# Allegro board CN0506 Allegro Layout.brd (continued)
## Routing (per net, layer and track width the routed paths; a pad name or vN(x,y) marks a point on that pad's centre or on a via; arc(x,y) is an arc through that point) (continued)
VDD_0P9: length 39.6
  TOP w0.508: C57.1 49.26,15.29 C58.1 50.01,15.27 ; C57.1 49.81,16.28 ; C57.1 49.26,16.87 ; 47.86,42.99 47.86,43 C22.1 46.83,43.78 ; 47.86,42.99 47.86,44.15 47.72,44.29 ; 47.86,42.99 C23.1 ; 49.24,39.83 v1(50.1,39.83) ; 49.24,39.83 C11.1 ; 49.24,39.83 C10.1 ; 46.2,36.36 C1.1 46.22,37.06 C2.1 ; C62.2 51.05,21.2 ; C62.2 49.79,22.25 ; C62.2 52.31,22.25 ; 49.77,47.32 C15.2 ; C15.2 52.46,47.32 ; C15.2 51.02,46.15 ; C61.1 48.51,22.3 ; C61.1 49.49,23.13 ; C61.1 47.53,23.13 ; 47.87,18.99 C69.1 46.86,18.43 ; 47.24,11.84 C49.1 47.22,12.48 C48.1 46.22,11.75 ; C14.1 49.59,47.82 ; C14.1 48.61,46.79 ; C14.1 47.63,47.82 ; C10.1 49.24,41.43 ; C10.1 49.78,40.84 ; 46.86,18.43 C70.1 ; 46.86,18.43 46.86,18.95 ; v1(47.21,35.98) C2.1 ; C2.1 47.87,37.06
  BOTTOM w0.279: U1.4 47.1,11.7 v1(46.99,11.58) ; U1.36 v1(50.28,15.27) ; v1(47.21,35.98) 47.21,36.12 47.07,36.26 U2.4 ; U1.28 v1(47.6,19.46)
  BOTTOM w0.305: U2.28 47.57,44.2 47.68,44.31 v1(47.68,44.32) ; v1(50.1,39.83) 50.09,39.83 U2.36
  BOTTOM w0.508: R55.2 10.1,51.5 ; R55.2 9.3,50.8 ; R55.2 v1(8.19,51.5)
  vias: v1(8.19,50.71) v1(18.35,57.19) v1(19.17,57.19) v1(20,57.15) v1(20,56.2) v1(20,55.18) v1(20.51,62.99) v1(20.51,62.1) v1(20.51,61.09) v1(20.51,60.07) v1(20.51,59.31) v1(20.89,57.15) v1(20.89,56.2) v1(20.89,55.18) v1(21.4,62.99) v1(21.4,62.1) v1(21.4,61.09) v1(21.4,60.07) v1(21.4,59.31)
VDD_ADJ: length 77.3
  TOP w0.203: U14.8 57.43,46.74 57.59,46.9 v1(57.59,47.79)
  TOP w0.229: U9.8 57.11,30.36 57.34,30.59 v1(57.34,30.92)
  TOP w0.305: U10.1 30.15,7.62 v1(30.43,7.34) ; U11.1 30.11,26.03 30.41,25.73 v1(30.41,25.53) ; U12.1 30.33,31.75 v1(30.54,31.54) ; U13.1 30.15,50.16 v1(30.43,49.89)
  TOP w0.508: R84.1 v1(58.54,28.62) ; 45.84,18.43 45.84,19.33 v1(46.05,19.54) ; 45.84,18.43 C68.1 ; 45.84,18.43 C66.1 ; C75.1 C76.1 62.16,9.78 61.62,10.33 v1(61.47,10.33) ; R8.1 v1(63.55,54.13) ; R80.1 v1(63.43,35.15) ; R77.1 v1(57.46,24.17) ; 44.52,23.65 C18.1 ; C18.1 42.46,23.65 ; C18.1 43.49,22.77 ; 49.26,13.26 C51.1 ; 49.26,13.26 C52.1 ; 49.26,13.26 49.26,13.23 49.69,13.23 v1(50.1,12.83) ; v1(60.2,9.06) 60.2,9.06 59.68,9.57 C74.1 ; R74.1 v1(68.01,33.06) ; C20.1 49.22,38.79 C13.1 49.22,37.64 v1(49.72,37.14) ; 45.7,21.99 45.7,21.03 ; 45.7,21.99 45.56,21.84 v1(44.51,21.84) ; 45.7,21.99 C19.2 45.51,22.71 44.51,22.71 ; 43.92,47.95 C65.1 ; C65.1 41.86,47.95 ; C65.1 42.9,47.04 ; 44.38,47.19 C67.2 45.69,46.09 ; v1(45.94,44.15) 45.82,44.02 C21.1 45.8,43 C12.1 ; R16.1 v1(63.31,50.84) ; R18.1 v1(56.07,50.84) ; R11.1 v1(56.19,43.22) ; C59.1 49.89,17.81 C60.1 49.93,17.81 50.6,17.81 v1(50.73,17.95) ; R86.1 v1(56.96,34.59) ; C5.1 48.89,42.52 C4.1 50.39,42.52 50.58,42.71 v1(50.59,42.71) ; R82.1 58.87,35.08 v1(58.61,35.35) ; R20.1 v1(56.07,53.38) ; R14.1 v1(63.56,46.53)
  BOTTOM w0.279: v1(46.05,19.54) 46.1,19.49 U1.25 ; v1(49.72,37.14) 49.72,37.57 49.45,37.83 U2.40 ; U1.31 50.05,17.77 50.22,17.95 v1(50.73,17.95) ; v1(50.1,12.83) 49.65,13.27 U1.40
  BOTTOM w0.305: U3.1 54.46,32.49 54.46,32.5 54.62,32.5 54.93,32.8 v1(54.93,32.98) ; v1(45.94,44.15) 46.07,44.02 U2.25 ; v1(50.59,42.71) 50.58,42.71 50.2,42.33 U2.31
  BOTTOM w0.508: 47.13,63.8 47.07,63.8 ; 47.13,63.8 v1(47.93,63.8) 47.91,63.82 C43.1 47.07,63.8 ; 47.13,63.8 47.13,63.79 v1(45.22,63.79) L2.2 ; 47.07,63.8 46.05,63.8 C41.1 v1(46.03,62.9) ; v1(35.32,63.82) C47.1 C45.1 ; R31.1 49.88,49.94 v1(49.88,51.56) ; R33.1 v1(49.97,26.3) ; v1(44.21,47.63) 44.45,47.87 R5.1 ; R6.1 v1(43.62,50.88) ; v1(43.96,22.61) 44.21,22.85 R71.1 ; v1(43.69,26.62) 43.62,26.62 R72.1 ; R37.1 46.83,49.94 v1(46.83,51.56) ; v1(32.23,64.81) L3.2 33.56,63.79 C45.1 ; P8.G39 v1(61.47,10.33) ; v1(33.59,62.9) C45.1 ; R39.1 v1(46.92,26.3) ; P8.H40 v1(60.2,9.06)
  vias: v1(42.51,46.81) v1(42.56,22.61) v1(44.23,46.86)
AUX_3P3: length 33.1
  TOP w0.305: U14.1 55.56,46.78 v1(55.24,47.09) ; U7.3 v1(67.88,17.53) ; U7.8 v1(66.58,26.84) ; U8.8 70.65,23.72 v1(70.42,23.49)
  TOP w0.508: Y1.6 41.11,30.91 C24.1 v1(42.86,30.16) ; Y2.6 C25.1 40.42,22.13 v1(40.17,21.88) ; v1(64.04,19.25) 64.45,18.84 C78.1
  BOTTOM w0.203: P8.D32 v1(64.04,19.25) ; v1(52.9,33.06) 52.9,32.66 53.1,32.46 U3.8 ; 30.32,28.31 30.39,28.23 R47.2
  BOTTOM w0.254: C27.1 22.16,30 U15.4
  BOTTOM w0.508: 52.35,50.64 Y3.1 Y3.6 ; Y3.6 53.95,50.64 ; Y3.6 54.7,51.44 ; C73.1 52.51,49.94 ; C73.1 53.78,49.94 ; C73.1 53.15,50.54 ; R26.1 v1(21.91,31.09) 21.9,31.09 C27.1 ; R49.2 30.39,29.38 ; R49.2 R47.2 ; R49.2 R76.1 30.39,30.52 ; R48.1 v1(20.9,28.3) ; 30.59,28.31 29.85,28.31 R47.2 ; U5.5 49.54,34.71 v1(50.07,35.25) ; R13.1 R47.2 ; v1(49.46,31.79) 49.46,31.41 49.08,31.03 U6.5 48.7,31.41 v1(48.7,31.79)
  vias: v1(31.05,29.63) v1(31.17,28.23) v1(32.19,30.9) v1(32.19,29.63) v1(32.19,27.34) v1(54.03,50.33) v1(54.03,49.57)
FB: length 4.2
  BOTTOM w0.203: U4.3 10.73,54.23 9.97,53.47 9.56,53.47 R55.1 7.75,53.2 R54.2
FMC_RESET_A: length 61
  BOTTOM w0.203: R58.1 49.04,53.09 50.83,54.88 50.83,61.08 52.01,62.26 R60.2 C42.1 57.67,63.78 62.04,59.42 62.04,36.23 61.54,35.74 60.19,35.74 P8.H19 57.84,36.36 56.32,34.84 56.32,33.31 55.08,32.07 54.26,32.07 U3.2
FMC_RESET_B: length 74.4
  BOTTOM w0.203: R58.2 44.9,54.05 41.59,57.36 41.59,61.63 40.96,62.26 R64.2 C46.1 40.94,63.78 43.49,66.33 55.7,66.33 62.67,59.36 62.67,35.09 62.02,34.44 60.21,34.44 P8.H20 59.14,35.09 58.87,34.82 58.83,34.82 55.67,31.66 U3.3
FPGA_LED_0_A: length 20.1
  TOP w0.203: v1(61.47,44.62) 60.89,44.04 60.89,43.22 55.94,38.27 55.94,33.82 56.04,33.72 56.04,32.07 56.32,31.79 57.59,31.79 57.96,31.42 57.96,30.61 57.31,29.96 U9.7
  BOTTOM w0.203: P8.G12 v1(61.47,44.62)
FPGA_LED_0_B: length 9.4
  TOP w0.203: v1(64.01,30.65) 63.33,31.32 58.81,31.32 58.37,30.88 58.37,30.28 57.66,29.57 56.92,29.57 U9.6
  BOTTOM w0.203: P8.D23 v1(64.01,30.65)
GA0: length 11.2
  TOP w0.203: U8.1 70.65,20.13 69.91,20.87 67.12,20.87 66.58,20.33 U7.1 66.58,17.41 65.93,16.76 65.92,16.76 65.84,16.68 v1(65.28,16.68)
  BOTTOM w0.203: P8.C34 v1(65.28,16.68)
GA1: length 15.7
  TOP w0.203: U8.2 71.3,17.94 70.96,17.6 69.88,17.6 69.53,17.95 69.53,20.16 69.33,20.36 67.44,20.36 67.23,20.16 U7.2 67.23,17.05 66.3,16.12 64.72,16.12 v1(64.01,15.41)
  BOTTOM w0.203: P8.D35 v1(64.01,15.41)
GP_CLK/RX_ER_A: length 24
  L6_SIG w0.203: v1(48.86,45.84) 56.79,45.84 57.51,46.56 61.82,46.56 64.01,48.75 v1(64.01,49.7)
  BOTTOM w0.203: U2.27 47.07,44.64 48.28,45.84 v1(48.86,45.84) 49.55,45.84 49.85,46.15 R29.1 ; v1(64.01,49.7) P8.D9
GP_CLK/RX_ER_B: length 40.4
  L6_SIG w0.203: v1(49.08,21.88) 58.6,21.88 59.04,22.31 68.82,22.31 69.66,23.15 69.66,30.08 v1(65.24,34.49)
  BOTTOM w0.203: R30.1 49.94,21.88 v1(49.08,21.88) 47.04,19.84 47.04,19.23 47.1,19.17 U1.27 ; v1(65.24,34.49) 64.64,33.89 P8.D21
INT_N/CRS_A: length 28.6
  L6_SIG w0.203: P4.1 44.18,44.77 44.18,43.57 45.58,42.18 49.77,42.18 50.05,41.89 57,41.89 58.45,43.35 v1(61.47,43.35)
  BOTTOM w0.203: P8.G13 v1(61.47,43.35) ; R6.2 43.26,48.55 43.26,46.46 43.28,46.45 P4.1 44.23,44.72 44.23,43.67 44.57,43.33 U2.22
INT_N/CRS_B: length 36.7
  L6_SIG w0.203: P7.1 44.01,21.36 44.26,21.12 45.53,21.12 47.43,23.03 56.32,23.03 56.91,23.61 59.18,23.61 60.91,25.33 60.91,25.8 61.39,26.28 65.64,26.28 65.85,26.48 65.85,28.49 65.52,28.82 64.57,28.82 v1(64.01,29.38)
  BOTTOM w0.203: U1.22 44.6,19.27 44.27,19.61 44.27,20.17 43.18,21.26 P7.1 43.23,21.41 43.23,23.62 R72.2 ; P8.D24 v1(64.01,29.38)
LED_0_A: length 49.9
  TOP w0.203: DS4.C 21.25,48.52 26.79,48.52 27.55,47.76 33.92,47.76 34.3,48.14 36.59,48.14 38.94,45.79 v1(40.25,45.79) ; U9.2 53.09,29.96 v1(52.89,29.76)
  L3_SIG w0.229: v1(52.89,29.76) 49.34,29.76 44.13,34.96 44.13,42.58 40.92,45.79 v1(40.25,45.79)
  BOTTOM w0.203: v1(40.25,45.79) 41.29,45.79 R4.2 R42.1
LED_0_B: length 50.8
  TOP w0.203: v1(54.42,27.22) 54.42,28.91 55.06,29.56 U9.3 ; DS2.C 20.19,27.74 25.27,27.74 25.52,27.99
  TOP w0.254: v1(39.3,20.95) 35.54,20.95 33.97,22.52 33.97,26.58 31.81,28.74 31.49,28.74 31.37,28.87 26.4,28.87 25.52,27.99
  L3_SIG w0.229: v1(54.42,27.22) 45.17,27.22 41.59,23.63 41.59,22.43 40.1,20.95 v1(39.3,20.95)
  BOTTOM w0.203: v1(39.3,20.95) R70.2 R41.1
LED_AL_A: length 23.6
  TOP w0.203: U13.6 27.46,51 26.6,51.86 10.41,51.86 M2.14
LED_AL_A_C2M: length 65
  TOP w0.203: v1(31.3,51.22) 31.08,51 U13.3
  L6_SIG w0.203: v1(31.3,51.22) 31.3,51.86 30.35,52.81 30.35,56.88 31.29,57.82 56.19,57.82 57.33,56.69 65.51,56.69 67.12,55.08 67.12,39.16 66.23,38.27 v1(65.28,38.27)
  BOTTOM w0.203: P8.D18 v1(65.28,38.27)
LED_AL_C: length 21.4
  TOP w0.203: M2.13 8.19,47.1 8.19,48.95 10.59,51.35 23.51,51.35 24.51,50.34 R25.2
LED_AL_C_C2M: length 57.6
  TOP w0.203: v1(31.3,50.2) 30.91,50.6 U13.2
  L6_SIG w0.203: v1(64.01,38.27) P8.D17 65.46,38.9 65.99,39.43 65.99,40.57 65.99,40.57 65.99,41.04 65.99,41.04 65.99,43.11 65.99,43.12 65.99,43.58 65.99,43.58 65.99,44.38 65.99,44.39 65.99,44.85 65.99,44.85 65.99,45.65 65.99,45.65 65.99,46.12 65.99,46.12 65.99,48.19 65.99,48.2 65.99,48.66 65.99,48.66 65.99,49.46 65.99,49.47 65.99,49.93 65.99,49.93 65.99,50.73 65.99,50.73 65.99,51.2 65.99,51.2 65.99,53.27 65.99,53.28 65.99,53.74 65.99,53.74 65.99,54.89 65.45,55.42 59.96,55.42 59.9,55.36 36.46,55.36 v1(31.3,50.2)
  BOTTOM w0.203: P8.D17 v1(64.01,38.27)
LED_AR_A: length 25.5
  TOP w0.203: U12.6 28.65,32.58 28.64,32.6 27.79,32.6 27.38,33.01 23.54,33.01 22.92,32.38 10.64,32.38 8.31,34.71 8.31,36.41 M2.12
LED_AR_A_C2M: length 38.3
  TOP w0.203: v1(31.73,33.95) 31.73,33.3 31.01,32.58 U12.3
  L6_SIG w0.203: v1(31.73,33.95) 31.73,34.79 35.34,38.39 49.46,38.39 50.3,39.23 51.04,39.23 52.7,37.57 60.39,37.57 60.83,38.01 60.83,38.9 v1(61.47,39.54)
  BOTTOM w0.203: P8.G16 v1(61.47,39.54)
LED_AR_C: length 18.9
  TOP w0.203: M2.11 10.35,31.84 24.42,31.84 R24.2
LED_AR_C_C2M: length 40.6
  TOP w0.203: v1(32.95,33.95) 31.18,32.18 29.93,32.18 29.92,32.19 U12.2
  L6_SIG w0.203: v1(61.47,40.81) 62.04,40.24 62.04,36.77 61.7,36.44 52.94,36.44 52.05,37.33 50.53,37.33 49.92,37.94 38.46,37.94 34.48,33.95 v1(32.95,33.95)
  BOTTOM w0.203: P8.G15 v1(61.47,40.81)
LED_BL_A: length 23.3
  TOP w0.203: U11.6 27.43,26.87 27.08,27.22 10.15,27.22 M1.14
LED_BL_A_C2M: length 39.3
  TOP w0.203: v1(33.08,25.06) 31.27,26.87 U11.3
  L6_SIG w0.203: v1(65.28,26.84) 64.96,26.84 64.32,27.47 62.92,27.47 62.54,27.85 60.73,27.85 60.35,27.47 58.73,27.47 55.69,24.42 35.75,24.42 35.11,25.06 v1(33.08,25.06)
  BOTTOM w0.203: P8.D27 v1(65.28,26.84)
LED_BL_C: length 21
  TOP w0.203: M1.13 8.31,22.84 8.31,24.64 10.35,26.67 23.98,26.67 24.51,26.14 R23.2
LED_BL_C_C2M: length 38.2
  TOP w0.203: U11.2 30.52,26.47 v1(32.57,24.42)
  L6_SIG w0.203: v1(32.57,24.42) 34.73,24.42 35.33,23.83 56.11,23.83 58.4,26.12 60.27,26.12 60.77,26.62 60.77,26.92 61.26,27.42 61.96,27.42 62.54,26.84 v1(64.01,26.84)
  BOTTOM w0.203: P8.D26 v1(64.01,26.84)
LED_BR_A: length 25.2
  TOP w0.203: M1.12 8.31,12.03 8.31,10.16 10.22,8.25 22.88,8.25 23.25,8.62 27.63,8.62 27.8,8.45 U10.6
LED_BR_A_C2M: length 72.1
  TOP w0.203: v1(60.2,37) 60.76,36.44 68.06,36.44 69.02,35.47 69.02,30.9 66.87,28.75 63.19,28.75 62.29,27.85 62.29,19.25 59.17,16.13 v1(58.61,16.13) ; v1(31.3,8.68) 31.08,8.45 U10.3
  L6_SIG w0.203: v1(58.61,16.13) 53.78,16.13 52.58,17.33 36.4,17.33 31.56,12.49 31.56,10.96 32.14,10.38 32.14,9.51 v1(31.3,8.68)
  BOTTOM w0.203: P8.G19 v1(60.2,37)
LED_BR_C: length 18.8
  TOP w0.203: R22.2 10.18,7.62 M1.11
LED_BR_C_C2M: length 71.9
  TOP w0.203: v1(31.3,7.66) 30.91,8.06 U10.2 ; v1(61.47,37) 68.51,37 70.04,35.47 70.04,30.39 67.12,27.47 63.22,27.47 62.92,27.18 62.92,19.09 58.61,14.77 v1(58.61,14.48)
  L6_SIG w0.203: v1(31.3,7.66) 31.61,7.66 33.26,9.31 33.26,11.9 34.95,13.59 50.7,13.59 52.03,14.91 53.35,14.91 53.78,14.48 v1(58.61,14.48)
  BOTTOM w0.203: P8.G18 v1(61.47,37)
LINK_ST_A: length 18.9
  L6_SIG w0.203: v1(58.89,47.12) 57.18,47.12 56.57,46.52 47.17,46.52 46.29,45.64 v1(46.29,45.09)
  BOTTOM w0.203: P8.H10 v1(58.89,47.12) ; R35.1 46.8,46.23 46.29,45.72 v1(46.29,45.09) 46.29,44.62 46.57,44.33 U2.26
LINK_ST_B: length 22
  L6_SIG w0.203: v1(46.41,20.83) 48.11,22.52 56.83,22.52 56.96,22.39 58.29,22.39 58.8,22.9 59.24,22.9 61.47,25.12 v1(61.47,25.57)
  BOTTOM w0.203: R36.1 46.92,21.34 v1(46.41,20.83) 46.61,20.63 46.61,19.31 46.6,19.3 46.6,18.69 46.6,18.69 U1.26 ; P8.G27 v1(61.47,25.57)
MDC_FMC_A: length 59.4
  TOP w0.229: v1(48.19,62.26) 47.57,61.63 43.49,61.63 42.22,60.36 42.22,55.92 40.95,54.65 v1(39.81,54.65)
  L6_SIG w0.203: v1(39.81,54.65) 41.72,54.65 44.08,52.29 44.08,51.27 45.02,50.33 45.02,45.81 v1(44.71,45.51) 44.71,43.88 45.84,42.75 49.84,42.75 50.36,43.27 52.21,43.27 53.02,42.46 56.7,42.46 58.15,43.9 61.82,43.9 62.03,43.7 62.03,42.96 61.8,42.74 61.15,42.74 59.64,41.23 59.64,40.25 v1(58.93,39.54)
  BOTTOM w0.203: v1(44.71,45.51) 44.71,43.9 45.07,43.54 U2.23 ; R56.1 39.8,53.76 39.81,53.77 v1(39.81,54.65) ; P8.H17 v1(58.93,39.54) ; R61.2 v1(48.19,62.26)
MDC_FMC_B: length 115.2
  L6_SIG w0.203: v1(36.13,62.23) 37.65,62.23 38.67,63.25 41.33,63.25 43.28,61.3 56.74,61.3 57.97,60.07 65.76,60.07 72.32,53.51 72.32,23.28 67.62,18.58 60.83,18.58 v1(60.2,19.22) 51.41,19.22 50.73,18.54 46.12,18.54 v1(44.83,19.84)
  BOTTOM w0.203: v1(44.83,19.84) 45.09,19.58 45.09,19.14 45.1,19.13 U1.23 ; P8.H32 v1(60.2,19.22) ; R56.2 36.13,55.76 v1(36.13,62.23) 36.1,62.26 R65.2
MDI_0A_N: length 28.9
  BOTTOM w0.102: M2.3 18.92,38.12 arc(18.86,38.06) 18.87,37.98 18.89,37.94 arc(18.89,37.94) 18.89,37.94 arc(18.9,37.92) 18.91,37.91 arc(19.21,37.63) 19.61,37.53 25.49,37.53 arc(25.69,37.49) 25.85,37.38 27.27,35.96 arc(27.36,35.9) 27.46,35.88 28.74,35.88 31.43,35.88 31.65,35.88 arc(31.75,35.92) 31.79,36.02 D1.3 31.79,37.7 arc(31.81,37.75) 31.84,37.8 31.85,37.82 arc(31.9,37.85) 31.96,37.86 37.58,37.86 arc(37.67,37.88) 37.74,37.93 38.39,38.57 arc(38.56,38.68) 38.75,38.72 42.64,38.72 arc(42.7,38.73) 42.75,38.77 42.77,38.78 arc(42.82,38.82) 42.88,38.83 U2.13
MDI_0A_P: length 28.9
  BOTTOM w0.102: M2.2 18.35,37.84 arc(18.52,37.86) 18.67,37.77 arc(18.67,37.76) 18.68,37.75 arc(19.08,37.38) 19.61,37.25 25.49,37.25 arc(25.58,37.23) 25.65,37.18 27.08,35.76 arc(27.26,35.64) 27.46,35.6 28.74,35.6 31.43,35.6 31.65,35.6 arc(31.66,35.6) 31.66,35.6 32.21,35.6 arc(32.84,35.86) 33.09,36.48 D1.1 33.09,37.48 arc(33.12,37.55) 33.2,37.58 37.58,37.58 arc(37.78,37.62) 37.94,37.73 38.59,38.38 arc(38.66,38.42) 38.75,38.44 42.64,38.44 arc(42.7,38.43) 42.75,38.39 42.77,38.38 arc(42.82,38.34) 42.88,38.33 U2.12
MDI_0B_N: length 29.2
  BOTTOM w0.102: U1.13 42.91,14.27 arc(42.84,14.26) 42.79,14.22 42.78,14.21 arc(42.72,14.17) 42.66,14.16 39.03,14.16 arc(38.83,14.12) 38.67,14.01 37.82,13.16 arc(37.75,13.11) 37.66,13.09 31.95,13.09 arc(31.84,13.05) 31.79,12.94 D4.3 31.79,11.22 arc(31.77,11.14) 31.69,11.11 28.98,11.11 arc(28.93,11.12) 28.89,11.15 26.98,13.06 arc(26.82,13.17) 26.62,13.21 19.29,13.21 arc(19.2,13.23) 19.13,13.28 18.96,13.44 arc(18.94,13.47) 18.92,13.5 18.87,13.59 arc(18.87,13.68) 18.92,13.74 M1.3
MDI_0B_P: length 29.2
  BOTTOM w0.102: M1.2 18.41,13.48 arc(18.49,13.5) 18.56,13.49 arc(18.61,13.46) 18.65,13.42 18.67,13.38 arc(18.71,13.31) 18.76,13.25 18.93,13.08 arc(19.1,12.97) 19.29,12.93 26.62,12.93 arc(26.71,12.91) 26.78,12.86 28.69,10.95 arc(28.82,10.87) 28.98,10.83 32.52,10.83 arc(32.57,10.84) 32.61,10.87 33.03,11.3 arc(33.08,11.36) 33.09,11.44 D4.1 33.09,12.62 arc(33.15,12.76) 33.29,12.82 37.66,12.82 arc(37.85,12.85) 38.02,12.96 38.87,13.81 arc(38.94,13.86) 39.03,13.88 42.66,13.88 arc(42.72,13.87) 42.78,13.83 42.79,13.82 arc(42.84,13.78) 42.91,13.77 U1.12
MDI_1A_N: length 28.1
  BOTTOM w0.102: M2.5 18.94,40.67 arc(18.89,40.6) 18.91,40.51 19.32,40.04 arc(19.39,39.99) 19.47,39.98 21.43,39.98 arc(21.61,40.05) 21.68,40.22 arc(21.88,40.43) 22.09,40.22 arc(22.16,40.05) 22.33,39.98 32.53,39.98 arc(32.93,39.81) 33.09,39.42 D1.6 33.09,38.72 arc(33.12,38.65) 33.2,38.62 36.85,38.62 arc(36.93,38.64) 37.01,38.69 37.89,39.57 arc(38.06,39.68) 38.25,39.72 42.64,39.72 arc(42.7,39.73) 42.75,39.77 42.77,39.78 arc(42.82,39.82) 42.88,39.83 U2.15
MDI_1A_P: length 28.1
  BOTTOM w0.102: M2.4 18.46,40.43 arc(18.56,40.44) 18.65,40.39 19.14,39.83 arc(19.18,39.79) 19.22,39.76 arc(19.34,39.71) 19.47,39.7 31.63,39.7 arc(31.75,39.65) 31.79,39.54 D1.4 31.79,38.51 arc(31.81,38.45) 31.84,38.4 31.85,38.39 arc(31.9,38.35) 31.96,38.34 36.85,38.34 arc(37.04,38.38) 37.21,38.49 38.09,39.38 arc(38.16,39.42) 38.25,39.44 42.64,39.44 arc(42.7,39.43) 42.75,39.39 42.77,39.38 arc(42.82,39.34) 42.88,39.33 U2.14
MDI_1B_N: length 28.4
  BOTTOM w0.102: M1.5 18.96,16.3 arc(18.88,16.21) 18.89,16.09 18.95,15.97 arc(18.97,15.94) 19,15.91 19.17,15.74 arc(19.24,15.69) 19.33,15.67 21.36,15.67 arc(21.49,15.73) 21.55,15.86 arc(21.6,15.99) 21.73,16.04 21.77,16.04 arc(21.9,15.99) 21.95,15.86 arc(22.01,15.73) 22.14,15.67 27.12,15.67 arc(27.31,15.63) 27.48,15.52 27.76,15.24 arc(27.8,15.21) 27.85,15.2 32.77,15.2 arc(33,15.11) 33.09,14.87 D4.6 33.09,14.05 arc(33.1,14.01) 33.11,13.96 arc(33.18,13.89) 33.29,13.86 36.9,13.86 arc(36.98,13.87) 37.06,13.92 38.15,15.01 arc(38.31,15.12) 38.51,15.16 42.66,15.16 arc(42.72,15.17) 42.78,15.21 42.79,15.22 arc(42.84,15.26) 42.91,15.27 U1.15
MDI_1B_P: length 28.4
  BOTTOM w0.102: U1.14 42.91,14.77 arc(42.84,14.78) 42.79,14.82 42.78,14.83 arc(42.72,14.87) 42.66,14.88 38.51,14.88 arc(38.42,14.86) 38.34,14.81 37.26,13.73 arc(37.09,13.62) 36.9,13.58 31.98,13.58 arc(31.85,13.63) 31.79,13.76 D4.4 31.79,14.82 arc(31.77,14.89) 31.69,14.92 27.85,14.92 arc(27.69,14.95) 27.56,15.04 27.28,15.33 arc(27.21,15.37) 27.12,15.39 19.33,15.39 arc(19.14,15.43) 18.97,15.54 18.8,15.71 arc(18.75,15.78) 18.7,15.85 18.65,15.96 arc(18.61,16.01) 18.56,16.03 18.54,16.04 arc(18.48,16.05) 18.43,16.03 M1.4
MDI_2A_N: length 30.2
  BOTTOM w0.102: U2.17 42.88,40.83 arc(42.82,40.82) 42.77,40.78 42.75,40.77 arc(42.7,40.73) 42.64,40.72 38.99,40.72 arc(38.9,40.74) 38.83,40.79 34.28,45.33 arc(34.12,45.44) 33.93,45.48 31.96,45.48 arc(31.84,45.43) 31.79,45.31 D2.3 31.79,43.66 arc(31.79,43.61) 31.77,43.56 arc(31.72,43.52) 31.65,43.5 28.26,43.5 arc(28.03,43.45) 27.84,43.32 27.19,42.68 arc(27.11,42.63) 27.03,42.61 19.38,42.61 arc(19.33,42.62) 19.29,42.65 18.93,43.07 arc(18.91,43.16) 18.96,43.22 M2.7
MDI_2A_P: length 30.2
  BOTTOM w0.102: M2.6 18.43,42.96 arc(18.58,42.98) 18.71,42.9 19.07,42.47 arc(19.21,42.37) 19.38,42.33 27.03,42.33 arc(27.22,42.37) 27.39,42.48 28.03,43.13 arc(28.14,43.2) 28.26,43.22 32.03,43.22 arc(32.78,43.53) 33.09,44.29 D2.1 33.09,45.1 arc(33.12,45.17) 33.2,45.2 33.93,45.2 arc(34.01,45.18) 34.09,45.13 38.63,40.59 arc(38.79,40.48) 38.99,40.44 42.64,40.44 arc(42.7,40.43) 42.75,40.39 42.77,40.38 arc(42.82,40.34) 42.88,40.33 U2.16
MDI_2B_N: length 30.2
  BOTTOM w0.102: M1.7 18.92,18.82 arc(18.87,18.76) 18.87,18.67 18.92,18.58 arc(18.94,18.55) 18.96,18.52 19.18,18.3 arc(19.25,18.25) 19.34,18.24 31.24,18.24 arc(31.63,18.4) 31.79,18.79 D5.3 31.79,20.55 arc(31.81,20.61) 31.84,20.66 31.85,20.67 arc(31.9,20.7) 31.96,20.71 33.85,20.71 arc(34.04,20.68) 34.21,20.57 38.55,16.23 arc(38.62,16.18) 38.71,16.16 42.66,16.16 arc(42.72,16.17) 42.78,16.21 42.79,16.22 arc(42.84,16.26) 42.91,16.27 U1.17
MDI_2B_P: length 30.1
  BOTTOM w0.102: M1.6 18.43,18.57 arc(18.48,18.59) 18.54,18.58 18.56,18.57 arc(18.61,18.55) 18.65,18.5 18.67,18.46 arc(18.71,18.39) 18.76,18.33 18.98,18.11 arc(19.15,18) 19.34,17.96 32.04,17.96 arc(32.11,17.96) 32.17,17.97 arc(32.22,17.99) 32.26,18.02 33.03,18.79 arc(33.07,18.83) 33.08,18.88 arc(33.09,18.94) 33.09,19.01 D5.1 33.09,20.24 arc(33.15,20.38) 33.29,20.44 33.85,20.44 arc(33.94,20.42) 34.01,20.37 38.35,16.03 arc(38.51,15.92) 38.71,15.88 42.66,15.88 arc(42.72,15.87) 42.78,15.83 42.79,15.82 arc(42.84,15.78) 42.91,15.77 U1.16
MDI_3A_N: length 30.4
  BOTTOM w0.102: U2.19 42.88,41.83 arc(42.82,41.82) 42.77,41.78 42.75,41.77 arc(42.7,41.73) 42.64,41.72 39.63,41.72 arc(39.54,41.74) 39.46,41.79 35.16,46.09 arc(34.99,46.2) 34.8,46.24 33.21,46.24 arc(33.13,46.27) 33.09,46.35 D2.6 33.08,46.91 arc(33.08,46.97) 33.08,47.02 33.08,47.22 arc(32.97,47.49) 32.7,47.6 28.13,47.6 arc(27.94,47.56) 27.77,47.45 25.54,45.22 arc(25.46,45.17) 25.38,45.15 22.51,45.15 arc(22.37,45.21) 22.31,45.35 arc(22.1,45.48) 21.9,45.35 arc(21.84,45.21) 21.7,45.15 19.37,45.15 arc(19.28,45.17) 19.2,45.22 arc(19.15,45.27) 19.11,45.32 18.91,45.6 arc(18.89,45.69) 18.95,45.76 M2.9
MDI_3A_P: length 30.4
  BOTTOM w0.102: U2.18 42.88,41.33 arc(42.82,41.34) 42.77,41.38 42.75,41.39 arc(42.7,41.43) 42.64,41.44 39.63,41.44 arc(39.43,41.48) 39.27,41.59 34.96,45.9 arc(34.89,45.94) 34.8,45.96 32.05,45.96 arc(31.87,46.04) 31.79,46.22 D2.4 31.79,47.07 arc(31.72,47.24) 31.55,47.32 28.13,47.32 arc(28.04,47.3) 27.97,47.25 25.74,45.02 arc(25.57,44.91) 25.38,44.87 19.37,44.87 arc(19.17,44.91) 19,45.03 arc(18.94,45.09) 18.89,45.16 18.69,45.43 arc(18.57,45.51) 18.43,45.5 M2.8
MDI_3B_N: length 29.9
  BOTTOM w0.102: U1.19 42.91,17.27 arc(42.84,17.26) 42.79,17.22 42.78,17.21 arc(42.72,17.17) 42.66,17.16 38.94,17.16 arc(38.85,17.18) 38.78,17.23 34.68,21.33 arc(34.51,21.44) 34.32,21.48 33.29,21.48 arc(33.15,21.53) 33.09,21.67 D5.6 33.09,22.43 arc(33.05,22.53) 32.95,22.57 29.16,22.57 arc(28.97,22.53) 28.8,22.42 27.19,20.81 arc(27.11,20.76) 27.03,20.74 22.02,20.74 arc(21.94,20.77) 21.91,20.84 arc(21.87,20.95) 21.76,20.99 21.66,20.99 arc(21.55,20.95) 21.51,20.84 arc(21.48,20.77) 21.41,20.74 19.27,20.74 arc(19.22,20.75) 19.17,20.78 19.07,20.89 arc(19.01,20.95) 18.97,21.02 18.91,21.14 arc(18.9,21.29) 19,21.4 M1.9
MDI_3B_P: length 29.9
  BOTTOM w0.102: M1.8 18.42,21.11 arc(18.55,21.12) 18.65,21.04 18.75,20.83 arc(18.78,20.78) 18.82,20.74 18.97,20.59 arc(19.11,20.49) 19.27,20.46 27.03,20.46 arc(27.22,20.5) 27.39,20.61 29,22.22 arc(29.07,22.27) 29.16,22.29 31.6,22.29 arc(31.74,22.23) 31.79,22.09 D5.4 31.79,21.34 arc(31.84,21.24) 31.94,21.2 34.32,21.2 arc(34.4,21.18) 34.48,21.13 38.58,17.03 arc(38.74,16.92) 38.94,16.88 42.66,16.88 arc(42.72,16.87) 42.78,16.83 42.79,16.82 arc(42.84,16.78) 42.91,16.77 U1.18
MDIO_FMC_A: length 66.3
  TOP w0.229: v1(42.86,54.61) 42.86,59.98 43.84,60.96 49.3,60.96 v1(50.61,62.26)
  L6_SIG w0.203: v1(42.86,54.61) 44.66,52.8 44.66,51.38 45.6,50.44 45.6,45.12 45.38,44.91 45.38,43.91 46.08,43.22 49.46,43.22 49.94,43.69 52.22,43.69 52.38,43.85 56.98,43.85 58.31,45.17 61.86,45.17 62.43,44.6 62.43,42.03 61.87,41.47 61.22,41.47 60.76,41 60.76,40.09 v1(60.2,39.54)
  BOTTOM w0.203: P8.H16 v1(60.2,39.54) ; R62.2 v1(50.61,62.26) ; v1(42.86,54.61) 42.86,53.77 42.85,53.76 R57.1 42.85,53.04 43.38,52.5 43.48,52.5 45.95,50.04 45.95,47.07 45.74,46.87 R5.2 45.27,44.03 45.57,43.72 U2.24
MDIO_FMC_B: length 111.6
  L6_SIG w0.203: v1(38.79,62.23) 41.08,62.23 43.12,60.19 56.33,60.19 57.08,59.44 65.46,59.44 71,53.9 71,22.98 67.95,19.93 64.5,19.93 63.94,20.49 v1(60.2,20.49) 55.81,20.49 55.11,21.18 48.17,21.18 47.08,20.1 45.71,20.1 v1(45.49,20.32)
  BOTTOM w0.203: P8.H31 v1(60.2,20.49) ; R57.2 41.85,54.42 41.07,55.21 39.26,55.21 38.81,55.67 38.81,62.22 v1(38.79,62.23) 38.76,62.26 R66.2 ; R71.2 45.53,20.91 45.49,20.88 v1(45.49,20.32) 45.49,19.31 45.6,19.2 U1.24
PG_C2M: length 40.7
  TOP w0.203: v1(64.01,58.59) 63.45,58.03 58.05,58.03 55.43,55.41 v1(55.43,49.7)
  BOTTOM w0.203: v1(55.43,49.7) 55.86,49.26 55.86,45.58 55.81,45.53 55.76,45.53 55.43,45.2 55.43,44.69 55.43,44.69 55.43,36.23 arc(55.41,36.13) 55.36,36.04 54.1,34.79 arc(54.02,34.73) 53.92,34.71 U5.1 50.68,34.71 50.22,34.25 50.22,31.24 50.44,31.03 U6.1 ; P8.D1 v1(64.01,58.59)
RESET_A: length 2.8
  BOTTOM w0.203: R1.1 47.69,31.67 48.83,32.81 U5.4
RESET_B: length 31.3
  BOTTOM w0.203: U6.4 49.08,28.36 49.84,27.6 51.62,27.6 54.09,25.13 arc(54.14,25.05) 54.16,24.95 54.16,9.16 arc(54.14,9.06) 54.09,8.98 52.26,7.16 R67.1
RX_CTL/RX_DV_A: length 26.8
  TOP w0.203: v1(58.93,42.08) R12.1 R11.2
  L3_SIG w0.203: v1(50.86,40.14) 51.21,39.79 52.26,39.79 53.02,40.55 53.39,40.55 53.59,40.35 53.59,40.12 53.79,39.92 54.2,39.92 54.41,40.12 54.41,43.52 54.61,43.73 55.03,43.73 55.23,43.52 55.23,41.14 55.43,40.93 55.72,40.93 55.92,41.14 55.92,42.32 56.13,42.52 56.48,42.52 56.7,42.3 56.7,41.94 56.83,41.81 57.14,41.81 57.34,42.01 57.34,44.41 57.54,44.62 57.97,44.62 58.23,44.36 58.23,42.07 58.43,41.87 58.72,41.87 v1(58.93,42.08)
  BOTTOM w0.203: P8.H14 v1(58.93,42.08) ; U2.35 49.81,40.33 49.87,40.39 50.61,40.39 v1(50.86,40.14)
RX_CTL/RX_DV_B: length 30.4
  TOP w0.203: v1(60.2,23.03) R78.1 R77.2
  L3_SIG w0.203: v1(51.5,15.24) 51.07,15.24 50.54,14.71 48.57,14.71 46.92,13.06 46.92,12.36 47.14,12.14 48.55,12.14 49.79,13.39 50.36,13.39 51.18,14.2 51.69,14.2 53.15,15.66 53.15,17.16 59.01,23.03 v1(60.2,23.03)
  BOTTOM w0.203: P8.H29 v1(60.2,23.03) ; v1(51.5,15.24) 50.91,15.83 50.05,15.83 49.99,15.77 U1.35
RXC/RX_CLK_A: length 26.7
  TOP w0.203: v1(61.47,52.24) R9.1 R8.2
  L3_SIG w0.203: v1(52,40.39) 53.65,42.04 53.65,44.11 55.3,45.76 57.31,45.76 57.99,46.44 62.47,46.44 62.74,46.72 62.74,50.96 v1(61.47,52.24)
  BOTTOM w0.203: U2.34 50.96,40.83 51.41,40.39 v1(52,40.39) ; P8.G6 v1(61.47,52.24)
RXC/RX_CLK_B: length 30.4
  TOP w0.203: R74.2 R75.1 v1(65.28,31.92)
  L3_SIG w0.203: v1(52.38,15.88) 52.38,17.12 56.57,21.31 56.57,24.3 58.1,25.82 58.1,26.8 58.75,27.45 58.75,27.98 59.5,28.72 59.5,30.84 60.02,31.36 64.72,31.36 v1(65.28,31.92)
  BOTTOM w0.203: P8.C22 v1(65.28,31.92) ; v1(52.38,15.88) 51.44,15.88 51.04,16.27 U1.34
RXD_0A: length 27
  TOP w0.203: R20.2 R21.1 v1(58.93,52.24)
  L3_SIG w0.203: v1(58.93,52.24) 60.7,52.24 60.91,52.03 60.91,52 61.24,51.68 61.26,51.68 62.16,50.78 62.16,47.99 61.96,47.79 58.48,47.79 57.22,46.53 54.81,46.53 52.64,44.36 52.64,41.82 52.15,41.33 v1(51.37,41.33)
  BOTTOM w0.203: v1(51.37,41.33) U2.33 ; P8.H7 v1(58.93,52.24)
RXD_0B: length 30.7
  TOP w0.203: v1(58.93,31.92) 58.1,32.74 R87.1 R86.2
  L3_SIG w0.203: v1(51.49,16.77) 50.89,16.17 49.34,16.17 48.95,16.55 48.95,17.39 50.73,19.17 50.73,20.36 52.76,22.39 52.76,23.41 53.4,24.04 54.54,24.04 56.45,25.95 56.45,27.22 56.78,27.55 56.81,27.55 57.13,27.87 57.13,28.91 56.7,29.34 56.7,31.92 57.21,32.42 57.97,32.42 58.48,31.92 v1(58.93,31.92)
  BOTTOM w0.203: v1(51.49,16.77) U1.33 ; P8.H22 v1(58.93,31.92)
RXD_1A: length 27
  TOP w0.203: v1(58.93,49.7) R19.1 R18.2
  L3_SIG w0.203: v1(52,42.46) 51.8,42.25 51.77,42.25 51.51,41.99 49.92,41.99 49.72,42.19 49.72,43.08 50.66,44.02 50.66,46.62 50.86,46.82 51.15,46.82 52.03,45.94 52.31,45.94 52.6,46.23 52.6,46.52 51.53,47.59 51.53,47.88 51.93,48.28 52.22,48.28 53.1,47.4 53.54,47.4 54.95,48.81 58.04,48.81 v1(58.93,49.7)
  BOTTOM w0.203: P8.H8 v1(58.93,49.7) ; v1(52,42.46) 51.41,42.46 50.78,41.83 U2.32
RXD_1B: length 30.2
  TOP w0.203: R84.2 59.37,29.71 59.63,29.97 R85.1 v1(58.93,30.65)
  L3_SIG w0.203: v1(52.38,18.03) 52.38,20.65 52.62,20.89 52.89,20.89 53.08,20.7 53.08,19.55 53.29,19.34 53.58,19.34 53.78,19.55 53.78,22.97 53.98,23.17 54.28,23.17 54.48,22.97 54.48,21.51 54.68,21.31 55.23,21.31 55.43,21.51 55.43,23.92 57.21,25.69 57.21,26.49 57.98,27.26 57.98,30.89 58.19,31.09 58.48,31.09 v1(58.93,30.65)
  BOTTOM w0.203: U1.32 51.11,17.27 51.88,18.03 v1(52.38,18.03) ; P8.H23 v1(58.93,30.65)
RXD_2A: length 25.6
  TOP w0.203: R16.2 R17.1 v1(60.2,49.7)
  L3_SIG w0.203: v1(49.46,44.7) 49.46,46.39 48.83,47.03 48.83,48.17 49.12,48.46 49.4,48.46 49.94,47.92 50.23,47.92 50.52,48.21 50.52,48.5 49.98,49.03 49.98,49.32 50.85,50.19 52.14,50.19 52.98,51.03 55.09,51.03 56.55,49.57 57.46,49.57 58.02,50.13 58.02,50.76 58.23,50.97 59.37,50.97 60.2,50.14 v1(60.2,49.7)
  BOTTOM w0.203: U2.30 48.57,43.17 49.42,44.02 49.42,44.03 49.46,44.07 v1(49.46,44.7) ; P8.G9 v1(60.2,49.7)
RXD_2B: length 30.7
  TOP w0.203: v1(60.2,33.19) 60.64,33.63 R83.1 R82.2
  L3_SIG w0.203: v1(49.46,20.07) 49.72,20.32 49.72,23.22 49.97,23.47 50.26,23.47 51.34,22.39 51.63,22.39 51.91,22.68 51.91,22.97 50.74,24.14 50.74,24.43 51.11,24.8 51.63,24.8 52.01,24.42 52.44,24.42 52.82,24.8 54.16,24.8 55.81,26.46 55.81,28.13 56.07,28.39 56.07,32.17 57.08,33.19 58.1,33.19 58.66,32.63 59.64,32.63 v1(60.2,33.19)
  BOTTOM w0.203: P8.G21 v1(60.2,33.19) ; U1.30 48.6,18.8 48.8,19.01 49.12,19.01 49.46,19.35 v1(49.46,20.07)
RXD_3A: length 26.7
  TOP w0.203: 62.42,48.43 62.42,48.43 R15.1 ; 62.42,48.43 62.42,47.91 R14.2 ; 62.42,48.43 v1(61.47,48.43)
  L3_SIG w0.203: v1(61.47,48.43) 61.47,50.52 60.38,51.6 52.23,51.6 51.64,51 50.26,51 47.94,48.68 47.94,45.97 v1(48.81,45.1)
  BOTTOM w0.203: v1(48.81,45.1) 48.31,44.6 48.31,44.14 48.07,43.91 U2.29 ; P8.G10 v1(61.47,48.43)
RXD_3B: length 29.3
  TOP w0.203: R80.2 R81.1 61.53,33.19 v1(61.5,33.22)
  L3_SIG w0.203: v1(61.5,33.22) 60.77,33.95 56.87,33.95 55.36,32.44 55.36,29.55 54.63,28.82 54.63,28.25 55.18,27.7 55.18,26.96 53.78,25.57 50.86,25.57 48.19,22.9 v1(48.19,20.07)
  BOTTOM w0.203: U1.29 48.1,19.17 48.19,19.26 v1(48.19,20.07) ; P8.G22 v1(61.5,33.22)
SCL: length 67.5
  TOP w0.203: R7.1 64.19,23.41 64.45,23.66 67.68,23.66 67.88,23.86 U7.6 67.88,26.08 v1(68.39,26.58) 68.51,26.71 71.31,26.71 71.95,26.07 U8.6
  TOP w0.229: v1(38.03,29.53) 38.03,29.5 38.41,29.12 Y2.2
  L6_SIG w0.203: v1(68.39,26.58) 68.39,28.61 66.99,30.01 57.34,30.01 56.07,31.28 53.06,31.28 52.3,30.52 47.68,30.52 45.73,32.47 40.97,32.47 v1(38.03,29.53) 36.99,29.53 36.19,30.33 30.75,30.33 29,28.57 29,27.67 28.23,26.9 26.92,26.9 26.6,27.22 v1(26.6,27.85)
  BOTTOM w0.203: R13.2 28.59,26.91 27.39,26.91 26.6,27.7 v1(26.6,27.85) 26.6,28.3 26.4,28.5 U15.10
SCLOUT1: length 22
  TOP w0.203: v1(38.79,36.62) 38.79,35.44 Y1.2
  L6_SIG w0.203: v1(28,28.23) 27.49,28.23 26.73,29 26.73,29.88 27.75,30.9 28.25,30.9 29.91,32.55 34.78,32.55 38.79,36.57 v1(38.79,36.62)
  BOTTOM w0.203: U15.9 26.85,29 27.62,28.23 v1(28,28.23) R47.1
SDA: length 79.5
  TOP w0.203: v1(68.51,23.53) 68.53,23.55 U7.5 ; v1(68.51,23.53) 68.51,24.82 U7.5 ; v1(68.51,23.53) 68.51,23.15 66.47,21.11 R10.1 ; U8.5 72.6,23.55 71.78,22.73 70.39,22.73 69.66,23.47 69.66,25.4 69.71,25.46 69.71,25.92 69.39,26.25 68.92,26.25 68.74,26.07 68.74,26.07 68.53,25.87 U7.5
  TOP w0.229: Y2.1 42.7,28.07 44.26,29.63 v1(44.26,33.06)
  L6_SIG w0.203: v1(68.51,23.53) 69.02,24.04 69.02,29.25 66.99,31.28 58.48,31.28 57.77,31.99 52.97,31.99 52.19,31.22 47.88,31.22 46.03,33.06 v1(44.26,33.06) 43.92,33.06 42.73,34.25 40.74,34.25 38.6,32.12 30.24,32.12 28.38,30.27 v1(28,30.27)
  BOTTOM w0.203: U15.7 26.85,30 27.11,30.27 v1(28,30.27) 28,30.27 28.25,30.52 R76.2
SDAOUT1: length 23.8
  TOP w0.203: v1(43.11,33.06) 43.11,34.66 42.71,35.06 Y1.1
  L6_SIG w0.203: v1(43.11,33.06) 40.48,33.06 38.95,31.54 31.35,31.54 29.32,29.5 v1(27.36,29.5)
  BOTTOM w0.203: U15.8 v1(27.36,29.5) 28.64,29.5 R49.1
TX_CTL/TX_EN_A: length 31.3
  L3_SIG w0.203: v1(52,39.12) 54.78,39.12 54.99,39.32 54.99,39.79 55.18,39.98 55.42,39.98 55.62,39.78 55.62,39.32 55.83,39.12 56.12,39.12 56.32,39.32 56.32,40.36 56.65,40.69 57.2,40.69 57.75,41.25 58.1,41.25 58.49,40.85 58.78,40.85 59.43,41.5 62.1,41.5 62.73,42.14 62.73,42.45 62.48,42.71 61.27,42.71 60.83,42.27 59.62,42.27 58.73,43.16 58.73,43.78 58.94,43.98 59.31,43.98 59.5,43.79 59.5,43.28 59.88,42.9 60.51,42.9 60.76,43.15 60.76,43.44 60.43,43.77 60.43,44.06 60.89,44.52 60.89,44.93 60.51,45.31 59.24,45.31 58.93,45 v1(58.93,44.62)
  BOTTOM w0.203: U2.37 49.8,39.33 49.87,39.27 50.33,39.27 50.34,39.28 51.84,39.28 v1(52,39.12) ; P8.H13 v1(58.93,44.62)
TX_CTL/TX_EN_B: length 39.5
  L3_SIG w0.203: v1(58.93,25.57) 58.35,24.99 58.35,23.79 58.56,23.58 58.96,23.58 59.17,23.79 59.17,24.73 59.37,24.93 59.78,24.93 59.98,24.73 59.98,23.79 60.18,23.58 60.69,23.58 60.89,23.38 60.89,18.9 60.58,18.58 59.43,18.58 59.11,18.9 59.11,21.17 58.91,21.38 58.37,21.38 58.16,21.17 58.16,17.12 57.95,16.91 57.54,16.91 57.34,17.11 57.34,19.39 57.13,19.6 56.71,19.6 56.51,19.39 56.51,17.11 56.31,16.91 55.83,16.91 55.62,17.11 55.62,17.74 55.42,17.95 55.06,17.95 54.86,17.74 54.86,16.97 54.67,16.78 53.97,16.78 53.67,16.49 53.67,15.01 v1(53.02,14.35)
  BOTTOM w0.203: U1.37 49.99,14.77 50.05,14.71 50.75,14.71 51.11,14.35 v1(53.02,14.35) ; P8.H28 v1(58.93,25.57)
TXC/TX_CLK_A: length 31.2
  L3_SIG w0.203: v1(58.93,45.89) 60.68,45.89 61.24,45.33 61.76,45.33 62.03,45.06 62.03,43.41 62.24,43.19 62.52,43.19 62.73,43.41 62.73,45.76 62.94,45.96 63.84,45.96 64.04,45.76 64.04,45.42 63.62,45 63.62,44.68 63.96,44.34 63.96,44.09 63.31,43.43 63.31,41.85 61.7,40.25 57.35,40.25 56.86,39.76 56.86,39.12 56.19,38.46 51.59,38.46 51.37,38.67 50.54,38.67 v1(50.54,38.67)
  BOTTOM w0.203: v1(50.54,38.67) 49.88,38.67 49.72,38.83 U2.38 ; P8.H11 v1(58.93,45.89)
TXC/TX_CLK_B: length 39.5
  L3_SIG w0.203: v1(61.47,24.3) 61.83,24.3 62.04,24.09 62.04,22.77 61.5,22.23 61.5,21.85 62.04,21.31 62.04,20.93 61.46,20.36 61.46,20.04 62.04,19.47 62.04,18.83 61.08,17.88 61.08,16.56 60.88,16.36 60.25,16.36 60.07,16.54 60.07,17.29 59.72,17.63 59.37,17.63 59.17,17.43 59.17,14 58.96,13.79 58.24,13.79 58.04,14 58.04,15.96 57.83,16.17 57.54,16.17 57.34,15.96 57.34,14.01 57.12,13.79 56.78,13.79 56.57,14 56.57,15.88 56.37,16.09 56.02,16.09 55.81,15.88 55.81,14 55.61,13.79 55.25,13.79 55.05,14 55.05,15.79 54.85,15.99 54.56,15.99 54.35,15.79 54.35,14.14 54.01,13.79 52.29,13.79 52.09,13.59 v1(51.49,13.59)
  BOTTOM w0.203: v1(51.49,13.59) 50.99,13.59 50.31,14.27 U1.38 ; P8.G28 v1(61.47,24.3)
TXD_0A: length 31.3
  L3_SIG w0.203: v1(64,42.07) 64,41.69 62.86,40.55 62.86,39.1 62.59,38.84 58.73,38.84 58.37,39.2 58.37,39.46 58.17,39.66 57.79,39.66 57.59,39.46 57.59,38.9 56.51,37.82 52.38,37.82 51.88,37.31 50.34,37.31 49.95,37.7 47.81,37.7 47.61,37.9 47.61,38.19 48.07,38.65 48.07,40.03 48.27,40.24 49.01,40.24 49.27,39.97 49.27,38.6 49.48,38.39 49.97,38.39 50.39,37.97 51.15,37.97 v1(51.24,37.89)
  BOTTOM w0.203: v1(64,42.07) P8.D14 ; v1(51.24,37.89) 51.15,37.97 50.01,37.97 49.65,38.33 U2.39
TXD_0B: length 39.5
  L3_SIG w0.203: v1(60.2,28.11) 60.2,27.61 60.4,27.4 61.58,27.4 61.78,27.61 61.78,28.74 62.1,29.06 62.67,29.06 62.95,28.78 62.95,15.56 59.55,12.15 58.59,12.15 57.4,10.96 51.75,10.96 51.37,11.34 51.37,11.72 51.75,12.1 52.76,12.1 53.02,12.36 v1(53.02,12.83)
  BOTTOM w0.203: v1(53.02,12.83) 50.99,12.83 50.04,13.77 U1.39 ; P8.H25 v1(60.2,28.11)
TXD_1A: length 31.3
  L3_SIG w0.203: v1(50.73,36.58) 50.43,36.58 50.22,36.37 50.22,35.88 50.57,35.54 51.3,35.54 51.53,35.76 51.53,36.46 51.77,36.7 52.15,36.7 52.32,36.53 52.32,35.73 52.49,35.55 53.07,35.55 53.27,35.76 53.27,37.03 53.48,37.23 53.8,37.23 53.97,37.06 53.97,35.8 54.17,35.6 54.59,35.6 54.8,35.8 54.8,37.05 55,37.25 55.3,37.25 55.5,37.06 55.5,36.68 55.69,36.49 56.32,36.49 57.78,37.95 58.07,37.95 58.27,37.74 58.27,37.33 58.47,37.12 58.89,37.12 59.09,37.33 59.09,37.5 59.29,37.71 61.58,37.71 62.29,37 62.73,37 63.02,37.28 63.02,37.52 62.85,37.69 62.42,37.69 62.24,37.87 62.24,38.15 62.42,38.33 63.05,38.33 63.43,38.71 63.43,40.23 v1(64.01,40.81)
  BOTTOM w0.203: P8.D15 v1(64.01,40.81) ; v1(50.73,36.58) 48.9,36.58 48.57,36.91 U2.1
TXD_1B: length 39.5
  L3_SIG w0.203: v1(49.49,12.21) 49.49,11.57 49.84,11.22 50.35,11.22 50.73,11.6 50.73,12.61 50.92,12.8 52.2,12.8 52.79,13.39 53.39,13.39 53.78,12.99 53.78,11.85 54.03,11.6 54.32,11.6 54.62,11.9 54.62,13.04 54.83,13.25 55.42,13.25 55.62,13.04 55.62,11.85 55.86,11.61 56.15,11.61 56.38,11.85 56.38,13.04 56.59,13.25 57.07,13.25 57.27,13.04 57.27,12.43 57.48,12.23 57.77,12.23 58.28,12.74 59.11,12.74 59.64,13.26 59.64,14.37 60.04,14.77 61.21,14.77 61.6,15.16 61.6,17.7 62.44,18.54 62.44,25.67 61.83,26.28 59.49,26.28 v1(58.93,26.84)
  BOTTOM w0.203: U1.1 48.6,12.41 48.8,12.21 v1(49.49,12.21) ; P8.H26 v1(58.93,26.84)
TXD_2A: length 31.3
  L3_SIG w0.203: v1(65.28,47.16) 64.69,46.56 64.69,38.12 62.92,36.36 59.5,36.36 59.24,36.62 58.1,36.62 57.3,35.81 56.28,35.81 55.43,34.96 51.88,34.96 51.6,34.69 49.49,34.69 48.95,35.22 48.95,35.73 49.17,35.94 v1(49.59,35.94)
  BOTTOM w0.203: P8.C10 v1(65.28,47.16) ; v1(49.59,35.94) 48.9,35.94 48.07,36.77 U2.2
TXD_2B: length 39.4
  L3_SIG w0.203: v1(61.47,30.65) 62.99,30.65 63.56,30.07 64.1,30.07 64.63,29.55 64.63,15.23 64.24,14.85 63.64,14.85 58.59,9.8 v1(51.35,9.8)
  BOTTOM w0.203: P8.G24 v1(61.47,30.65) ; U1.2 48.1,11.52 49.3,10.33 50.82,10.33 v1(51.35,9.8)
TXD_3A: length 31.2
  L3_SIG w0.203: v1(65.28,45.89) 65.85,45.32 65.85,38.01 64.19,36.36 63.85,36.36 63.28,35.79 59.31,35.79 59.11,35.98 58.45,35.98 57.69,35.22 56.58,35.22 55.69,34.33 52.13,34.33 51.94,34.14 49.15,34.14 v1(47.94,35.35)
  BOTTOM w0.203: U2.3 47.57,36.66 47.94,36.3 v1(47.94,35.35) ; P8.C11 v1(65.28,45.89)
TXD_3B: length 39.4
  L3_SIG w0.203: v1(50.1,9.69) 49.35,9.69 49.15,9.89 49.15,10.18 49.35,10.39 58.54,10.39 63.43,15.28 63.43,29.12 62.8,29.76 61.85,29.76 v1(61.47,29.38)
  BOTTOM w0.203: U1.3 47.6,11.13 49.04,9.69 v1(50.1,9.69) ; P8.G25 v1(61.47,29.38)
UNNAMED_2_ADIN1300_I19_CLK25REF: length 3
  BOTTOM w0.203: U2.6 46.07,36.28 46.83,35.52 CLK25A.1
UNNAMED_2_ADIN1300_I19_LED0: length 3.6
  BOTTOM w0.203: U2.21 44.07,43.17 43.05,44.2 41.98,44.2 R4.1
UNNAMED_2_ADIN1300_I19_RESETN: length 7.1
  TOP w0.508: C3.1 45.18,36.21 v1(45.57,35.81)
  BOTTOM w0.203: U2.7 v1(45.57,35.81) 45.57,32.75 R2.2 R1.2
UNNAMED_2_ADIN1300_I19_REXT: length 1.5
  BOTTOM w0.305: R3.2 43.74,35.85 43.74,36.41 44.07,36.75 U2.10
UNNAMED_2_ADLTC4316_I318_ENABLE: length 1.7
  BOTTOM w0.254: U15.5 23.05,30.5 22.79,30.76 22.79,31.8 R26.2
UNNAMED_2_ADLTC4316_I318_XORL: length 2.5
  BOTTOM w0.254: R27.1 21.9,28.22 R48.2 22.28,29.5 U15.3
UNNAMED_4_CAP_I33_N2: length 3.1
  BOTTOM w0.508: C34.2 23.04,11.72 M1.1
UNNAMED_4_DIOLED_I25_P: length 1.3
  TOP w0.203: DS2.A 18.91,29.33 R28.1
UNNAMED_4_ICNLSV2T240_I38_B1: length 2.6
  TOP w0.203: U11.7 27.8,26.47 27.36,26.03 R23.1
UNNAMED_4_ICNLSV2T240_I41_B1: length 2.6
  TOP w0.203: R22.1 27.36,7.62 27.8,8.06 U10.7
UNNAMED_6_RES_I1_N2: length 2.2
  BOTTOM w0.203: R29.2 R31.2 R32.1
UNNAMED_6_RES_I11_N2: length 2.2
  BOTTOM w0.203: R35.2 R37.2 R38.1
UNNAMED_6_RES_I12_N2: length 2.2
  BOTTOM w0.203: R42.2 R45.2 R46.1
UNNAMED_6_RES_I14_N2: length 2.2
  BOTTOM w0.203: R40.1 R39.2 R36.2
UNNAMED_6_RES_I17_N2: length 2.2
  BOTTOM w0.203: R44.1 R43.2 R41.2
UNNAMED_6_RES_I21_N2: length 2.2
  BOTTOM w0.203: R34.1 R33.2 R30.2
UNNAMED_7_CAP_I72_N2: length 3
  BOTTOM w0.508: M2.1 22.95,36.11 C26.2
UNNAMED_7_DIOLED_I63_P: length 1.3
  TOP w0.203: DS4.A 20.01,48.85 R53.1
UNNAMED_7_ICNLSV2T240_I75_B1: length 2.6
  TOP w0.203: R24.1 26.42,31.75 26.86,32.19 U12.7
UNNAMED_7_ICNLSV2T240_I76_B1: length 2.6
  TOP w0.203: U13.7 27.8,50.6 27.36,50.16 R25.1
UNNAMED_9_74109V2_I253_B: length 3.2
  BOTTOM w0.203: U3.6 52.59,31.66 52.38,31.45 52.38,30.38 52.08,30.08 U6.2
UNNAMED_9_74109V2_I254_B: length 3.4
  BOTTOM w0.203: U3.7 52.54,32.06 52.34,32.26 52.34,33.56 52.14,33.76 U5.2
UNNAMED_9_ADLT3502_I252_BOOST: length 1.9
  BOTTOM w0.254: U4.7 11.18,58.67 C38.1
UNNAMED_10_CAP_I161_N1: length 2.7
  BOTTOM w0.508: R59.2 42.76,61.61 C40.1 42.76,63.73 L2.1
UNNAMED_10_CAP_I224_N1: length 2.7
  BOTTOM w0.508: L3.1 30.7,63.73 C44.1 30.7,61.61 R63.2
UNNAMED_10_CN8PODDEVENV2_I25_N1: length 2.4
  BOTTOM w0.508: R59.1 44.12,59.39 P6.1
UNNAMED_10_CN8PODDEVENV2_I25_N2: length 2.2
  BOTTOM w0.203: R61.1 47.02,61.24 P6.3
UNNAMED_10_CN8PODDEVENV2_I25_N3: length 2.2
  BOTTOM w0.203: R62.1 49.59,60.64 49.56,60.61 P6.5
UNNAMED_10_CN8PODDEVENV2_I25_N4: length 2.2
  BOTTOM w0.203: P6.7 52.1,60.61 52.13,60.64 R60.1
UNNAMED_10_CN8PODDEVENV2_I223_1: length 2.2
  BOTTOM w0.203: R65.1 34.96,61.24 P2.3
UNNAMED_10_CN8PODDEVENV2_I223_2: length 2.2
  BOTTOM w0.203: R66.1 37.52,59.06 P2.5
UNNAMED_10_CN8PODDEVENV2_I223_3: length 2.2
  BOTTOM w0.203: P2.7 40.04,60.61 40.06,60.64 R64.1
UNNAMED_10_CN8PODDEVENV2_I223_N: length 2.4
  BOTTOM w0.508: P2.1 32.06,59.39 R63.1
UNNAMED_12_ADIN1300_I137_CLK25R: length 3.1
  BOTTOM w0.203: U1.6 46.1,11.66 46.99,10.78 CLK25B.1
UNNAMED_12_ADIN1300_I137_LED0: length 3.6
  BOTTOM w0.203: U1.21 44.1,18.76 43.52,19.34 42.58,19.34 41.97,19.95 R70.1
UNNAMED_12_ADIN1300_I137_RESETN: length 7
  TOP w0.508: v1(45.6,11.3) 45.21,11.7 C50.1
  BOTTOM w0.203: U1.7 v1(45.6,11.3) 45.6,8.21 R68.2 R67.2
UNNAMED_12_ADIN1300_I137_REXT: length 2.4
  BOTTOM w0.305: R69.2 43.68,11.7 44.1,12.13 U1.10
UNNAMED_13_CN160PCDGH_I191_N30: length 1.3
  BOTTOM w0.203: P8.D30 P8.D31
UNNAMED_13_CN160PCDGH_I193_N30: length 2.2
  TOP w0.203: v1(65.28,21.76) 64.63,22.4 R7.2
  BOTTOM w0.203: P8.C30 v1(65.28,21.76)
UNNAMED_13_CN160PCDGH_I193_N31: length 2.1
  TOP w0.203: R10.2 64.9,20.11 v1(65.28,20.49)
  BOTTOM w0.203: P8.C31 v1(65.28,20.49)
UNNAMED_13_CN160PCDGH_I222_N4: length 6.4
  BOTTOM w0.203: P8.H4 56.61,55.41 54.74,53.54 Y3.4
UNNAMED_13_CN160PCDGH_I222_N5: length 6.3
  BOTTOM w0.203: Y3.5 55.18,52.49 55.51,52.82 56.65,52.82 57.97,54.14 P8.H5
XTAL_I_A: length 21.9
  TOP w0.203: Y1.4 v1(35.87,29.6)
  BOTTOM w0.203: v1(35.87,29.6) 35.87,31.33 36.08,31.54 36.48,31.54 36.69,31.33 36.69,30.72 36.89,30.52 37.3,30.52 37.5,30.72 37.5,31.33 37.7,31.54 38.11,31.54 38.31,31.33 38.31,30.72 38.52,30.52 38.92,30.52 39.13,30.72 39.13,31.33 39.33,31.54 39.73,31.54 39.94,31.33 39.94,30.72 40.14,30.52 40.55,30.52 40.75,30.72 40.75,31.33 40.95,31.54 43.62,31.54 44.81,32.73 44.81,35.55 44.57,35.79 U2.9
XTAL_I_B: length 22
  TOP w0.203: Y2.4 35.87,22.77 37.02,21.63 39.41,21.63 39.86,21.18 39.86,19.8 v1(40.7,18.96)
  L3_SIG w0.203: v1(44.6,10.83) 44.6,17.43 42.43,19.6 41.33,19.6 v1(40.7,18.96)
  BOTTOM w0.203: v1(44.6,10.83) U1.9
XTAL_REF_A: length 35.6
  TOP w0.203: v1(53.53,33.57) 54.29,34.33 54.29,45.51 55.12,46.34 U14.2 ; v1(38.92,29.53) 38.92,30.55 Y1.5
  L3_SIG w0.203: v1(53.53,33.57) 53.69,33.4 53.69,29.77 52.92,29 49.4,29 49.02,28.61 39.81,28.61 38.92,29.5 v1(38.92,29.53)
XTAL_REF_A_FMC: length 14.1
  TOP w0.203: v1(64.01,50.96) 64.61,50.36 64.61,46.42 63.94,45.76 62.42,45.76 61.65,46.52 58.23,46.52 58.05,46.34 U14.7
  BOTTOM w0.203: v1(64.01,50.96) 64.01,50.96 P8.D8
XTAL_REF_B: length 38.5
  TOP w0.203: U14.3 55.36,45.94 54.8,45.38 54.8,33.95 v1(54.42,33.57) ; Y2.5 38.16,23.82 v1(38.16,22.52)
  L3_SIG w0.203: v1(38.16,22.52) 40.06,24.42 40.06,25.31 42.43,27.67 46.73,27.67 52.17,27.67 54.16,29.66 54.16,33.31 v1(54.42,33.57)
XTAL_REF_B_FMC: length 21.2
  TOP w0.203: v1(64.01,35.73) 63.75,35.98 60,35.98 59.48,36.5 59.48,38.03 59.49,38.03 59.49,40.92 61.35,42.79 61.7,42.79 62.16,43.25 62.16,45 61.83,45.33 58.66,45.33 58.04,45.94 U14.6
  BOTTOM w0.203: v1(64.01,35.73) P8.D20

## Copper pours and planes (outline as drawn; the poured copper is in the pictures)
AGND_A on TOP: 12.9,49.7 17.71,49.7 17.71,48.44 13.52,44.24 13.52,35.72 17.71,31.53 17.71,30.01 1.27,30.01 1.27,47.28 10.48,47.28 ; 2 cut-outs
AGND_A on BOTTOM, L2_GND, L3_SIG, L4_GND, L7_GND: 1.27,30.01 1.27,47.28 10.48,47.28 12.9,49.7 17.71,49.7 17.71,48.44 13.52,44.24 13.52,35.72 17.71,31.53 17.71,30.01
AGND_A on L5_PWR, L6_SIG: 12.9,49.7 17.71,49.7 17.71,48.44 13.71,44.43 13.57,44.22 13.52,43.98 13.52,35.98 13.57,35.74 13.71,35.53 17.71,31.53 17.71,30.01 1.27,30.01 1.27,47.28 10.22,47.28 10.46,47.33 10.67,47.47
AGND_B on TOP: 1.27,4.57 1.27,28.74 17.71,28.74 17.71,24.05 13.52,19.86 13.52,11.21 15.93,8.79 15.93,4.57 ; 2 cut-outs
AGND_B on BOTTOM, L2_GND, L3_SIG, L4_GND, L7_GND: 1.27,4.57 1.27,28.74 17.71,28.74 17.71,24.05 13.52,19.86 13.52,11.21 15.93,8.79 15.93,4.57
AGND_B on L5_PWR, L6_SIG: 1.27,28.74 17.71,28.74 17.71,24.05 13.71,20.05 13.57,19.84 13.52,19.6 13.52,11.47 13.57,11.23 13.71,11.02 15.93,8.79 15.93,4.57 1.27,4.57
AVDD_3P3 on BOTTOM: 40.57,8.93 40.57,6.9 42.86,6.9 42.86,8.93
AVDD_3P3 on L3_SIG: 42.35,47.79 34.73,47.79 34.73,7.79 43.62,7.79 43.62,18.71 43.49,18.84 40.45,18.84 40.45,22.9 38.03,22.9 38.03,35.22 43.24,35.22 43.24,43.47 42.35,44.36
AVDD_3P3 on L5_PWR: 54.16,30.58 54.36,30.65 54.47,30.84 55.62,30.84 55.62,6.83 40.64,6.83 40.64,11.91 51.49,11.91 51.72,12.01 51.81,12.23 51.81,30.58
DGND on TOP: outline of 112 points within 1.27,1.27 77.53,67.73 ; 24 cut-outs
DGND on BOTTOM: 18.37,67.73 77.53,67.73 77.53,1.27 23.17,1.27 23.17,2.3 22.51,3.91 20.9,4.57 17.2,4.57 17.2,9.32 14.79,11.73 14.79,19.33 18.98,23.52 18.98,32.05 14.79,36.24 14.79,43.72 18.98,47.91 18.98,49.7 22.04,49.7 22.06,49.72 22.29,49.72 22.48,49.91 22.48,63.82 11.6,63.82 11.55,63.87 11.28,63.87 11.23,63.82 8.31,63.82 8.12,63.63 8.12,59.18 10.09,57.21 10.4,57.21 10.4,56.3 10.47,56.23 11.93,56.23 12.79,57.09 17.21,57.09 17.27,57.15 17.27,55.12 15.97,55.12 15.77,55.32 13.72,55.32 13.34,54.95 12.21,54.95 11.96,55.2 11.96,55.48 11.84,55.6 10.66,55.6 10.63,55.6 10.42,55.39 10.42,54.21 9.65,53.43 9.65,52.55 7.97,52.55 7.97,54.14 6.09,54.14 6.09,52.34 6.22,52.34 6.22,52.34 6.98,52.34 6.98,48.55 1.27,48.55 1.27,63.03 5.3,63.03 6.84,63.63 7.56,65.13 16.1,65.13 17.71,65.79 18.37,67.4 ; 51 cut-outs
DGND on L2_GND: 23.17,1.27 23.17,2.3 22.51,3.91 20.9,4.57 17.2,4.57 17.2,9.32 14.79,11.73 14.79,19.33 18.98,23.52 18.98,32.05 14.79,36.24 14.79,43.72 18.98,47.91 18.98,50.59 18.61,50.97 12.37,50.97 9.96,48.55 1.27,48.55 1.27,63.03 5.3,63.03 6.84,63.63 7.56,65.13 16.1,65.13 17.71,65.79 18.37,67.4 18.37,67.73 77.53,67.73 77.53,1.27
DGND on L3_SIG: 23.17,1.27 23.17,2.3 22.51,3.91 20.9,4.57 17.2,4.57 17.2,9.32 14.79,11.73 14.79,19.33 18.98,23.52 18.98,32.05 14.79,36.24 14.79,43.72 18.98,47.91 18.98,50.59 18.61,50.97 12.37,50.97 9.96,48.55 1.27,48.55 1.27,63.03 5.3,63.03 6.84,63.63 7.56,65.13 16.1,65.13 17.71,65.79 18.37,67.4 18.37,67.73 77.53,67.73 77.53,1.27 ; 44 cut-outs
DGND on L4_GND: 23.17,1.27 23.17,2.3 22.51,3.91 20.9,4.57 17.2,4.57 17.2,9.32 14.79,11.73 14.79,19.33 18.98,23.52 18.98,32.05 14.79,36.24 14.79,43.72 18.98,47.91 18.98,50.59 18.61,50.97 12.37,50.97 9.96,48.55 1.27,48.55 1.27,63.03 5.3,63.03 6.84,63.63 7.56,65.13 16.1,65.13 17.71,65.79 18.37,67.4 18.37,67.73 77.53,67.73 77.53,1.27
DGND on L6_SIG: 77.53,67.73 77.53,1.27 69.34,1.27 69.34,12.23 69.25,12.46 69.02,12.55 62.8,12.55 62.57,12.46 62.48,12.23 62.48,8.61 43.75,8.61 43.52,8.52 43.43,8.29 43.43,6.07 29.21,6.07 29.21,20.18 33.64,24.61 43.07,24.61 43.07,26.42 46.48,26.42 46.61,26.55 46.61,32.55 46.51,32.78 46.29,32.87 42.15,32.87 39,29.73 29.54,29.73 29.54,43.35 39.35,43.35 39.58,43.44 39.67,43.66 39.67,49.24 41.97,49.24 42.19,49.33 42.29,49.56 42.29,51.35 42.27,51.46 42.2,51.56 40.93,52.96 40.83,53.03 40.7,53.06 29.84,53.06 29.84,54.78 29.75,55 29.52,55.09 9.58,55.09 9.46,55.07 9.36,55 8.98,54.62 8.91,54.52 8.89,54.4 8.89,48.55 1.27,48.55 1.27,63.03 5.3,63.03 6.84,63.63 7.56,65.13 16.1,65.13 17.71,65.79 18.37,67.4 18.37,67.73 ; 26 cut-outs
DGND on L7_GND: 23.17,1.27 23.17,2.3 22.51,3.91 20.9,4.57 17.2,4.57 17.2,9.32 14.79,11.73 14.79,19.33 18.98,23.52 18.98,32.05 14.79,36.24 14.79,43.72 18.98,47.91 18.98,50.59 18.61,50.97 12.37,50.97 9.96,48.55 1.27,48.55 1.27,63.03 5.3,63.03 6.84,63.63 7.56,65.13 16.1,65.13 17.71,65.79 18.37,67.4 18.37,67.73 77.53,67.73 77.53,1.27
DVDD_3P3 on BOTTOM: 10.28,52.55 10.28,53.17 11.06,53.95 11.06,55.39 11.05,55.4 11.75,55.4 11.76,55.39 11.76,54.76 12,54.52 13.67,54.52 13.81,54.66 15.87,54.66 15.87,53.06 11.36,53.06 10.85,52.55
DVDD_3P3 on BOTTOM: 40.57,6.39 40.57,4.36 42.86,4.36 42.86,6.39
DVDD_3P3 on L6_SIG: 9.72,54.46 29.21,54.46 29.21,52.74 29.3,52.52 29.52,52.43 40.56,52.43 41.65,51.22 41.65,49.87 39.35,49.87 39.13,49.78 39.04,49.56 39.04,43.98 29.22,43.98 28.99,43.89 28.9,43.66 28.9,32.56 26.09,29.76 26.09,26.96 26.73,26.33 28.38,26.33 31.05,29 39.3,29 42.22,31.92 45.97,31.92 45.97,27.22 42.1,27.22 42.1,25.25 32.95,25.25 28.57,20.87 28.57,5.75 28.66,5.53 28.89,5.44 43.75,5.44 43.97,5.53 44.07,5.75 44.07,7.98 62.8,7.98 63.02,8.07 63.12,8.29 63.12,11.91 68.7,11.91 68.7,1.27 23.17,1.27 23.17,2.3 22.51,3.91 20.9,4.57 17.2,4.57 17.2,9.06 17.16,9.3 17.02,9.51 14.79,11.73 14.79,19.33 18.8,23.34 18.93,23.55 18.98,23.79 18.98,31.79 18.93,32.03 18.8,32.24 14.79,36.24 14.79,43.72 18.8,47.72 18.93,47.93 18.98,48.17 18.98,50.33 18.8,50.78 18.35,50.97 12.63,50.97 12.39,50.92 12.18,50.78 9.96,48.55 9.52,48.55 9.52,54.26 ; 1 cut-out
VDD_0P9 on TOP: 20.05,63.79 27.33,63.79 30.35,60.78 30.35,54.6 54.16,54.6 54.16,10.35 45.92,10.35 45.92,12.79 49.55,12.79 49.55,13.63 49.76,13.63 49.76,16.26 49.55,16.26 49.55,16.7 48.71,16.7 48.71,18.78 46.43,18.78 46.43,22.8 47.16,22.8 47.16,23.69 52.47,23.69 52.47,27.67 48.38,27.67 48.38,35.34 45.95,35.34 45.95,37.4 49.5,37.4 49.5,39.03 49.73,39.03 49.73,41.07 49.5,41.07 49.5,41.29 48.89,41.29 48.89,43.32 46.35,43.32 46.35,44.56 47.27,44.56 47.27,48.43 52.32,48.43 52.32,52.57 20.25,52.55 10.41,52.55 7.87,50.01 7.36,50.01 7.36,57.44 9.84,59.92 16.19,59.92
VDD_0P9 on BOTTOM: 7.62,48.55 7.62,51.92 11.11,51.92 11.62,52.43 16.51,52.43 16.51,54.29 17.9,54.29 17.9,58.92 18.28,59.3 18.28,63.18 21.84,63.18 21.84,50.97 12.37,50.97 9.96,48.55
VDD_ADJ on TOP: 46.88,48.01 44.08,48.01 43.57,48.52 41.54,48.52 41.54,47.13 43.83,44.84 46.37,44.84 46.88,45.35
VDD_ADJ on TOP: 46.62,23.12 45.48,23.12 44.34,24.27 42.18,24.27 42.18,22.11 44.21,20.07 45.61,20.07 46.62,21.09
VDD_ADJ on L5_PWR: outline of 110 points within 1.27,1.27 77.53,67.73 ; 1 cut-out
AUX_3P3 on BOTTOM: 54.99,51.98 51.88,51.98 51.88,49.82 52,49.7 53.78,49.7 53.78,49.19 54.99,49.19
AUX_3P3 on BOTTOM: 29.4,31.15 29.4,26.46 32.95,26.46 32.95,31.15
AUX_3P3 on L5_PWR: 51.94,50.9 55.11,50.9 55.11,48.55 55.21,48.33 55.43,48.24 55.88,48.24 55.88,45.95 55.43,45.95 55.21,45.86 55.11,45.63 55.11,42.2 55.21,41.98 55.43,41.89 72.51,41.89 72.51,16.74 62.73,16.74 62.73,30.33 69.02,30.33 69.25,30.42 69.34,30.65 69.34,36.62 69.25,36.84 69.02,36.93 56.96,36.93 56.83,36.91 56.73,36.84 53.94,34.05 53.87,33.94 53.84,33.82 53.84,31.22 46.8,31.22 46.67,31.19 46.57,31.12 41.36,25.92 41.3,25.81 41.27,25.69 41.27,21.44 37.08,21.44 37.08,26.71 36.99,26.93 36.76,27.03 30.86,27.03 30.86,30.2 31.43,30.2 31.65,30.29 31.75,30.52 31.75,32.3 31.65,32.52 31.43,32.61 23.05,32.61 22.82,32.52 22.73,32.3 22.73,27.92 18.98,27.92 18.98,31.79 18.93,32.03 18.8,32.24 14.79,36.24 14.79,38.84 45.34,38.84 45.34,36.36 45.43,36.14 45.65,36.04 49.97,36.04 50.09,36.07 50.2,36.14 51.85,37.79 51.92,37.89 51.94,38.01
UNNAMED_9_ADLT3502_I252_DA on BOTTOM: 10.6,56.54 10.6,57.29 10.54,57.36 10.54,57.66 8.76,59.44 8.76,63.18 11.1,63.18 11.1,59.97 10.46,59.34 10.46,58.31 10.85,57.92 10.85,56.54
UNNAMED_9_CAP_I244_N2 on BOTTOM: 11.49,56.54 11.49,57.92 11.92,58.35 11.92,59.08 11.73,59.28 11.73,63.18 16.89,63.18 16.89,57.72 12.76,57.72 11.75,56.72 11.75,56.54

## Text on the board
Ref Des/Silkscreen Bottom: A | C
Ref Des/Silkscreen Top: EVAL-CN0506-FMCZ | A | C | LED_OB | LED_OA | MDIO_B | MDIO_A | 0 | 1
PAGE_OUTLINE: B | AS PER ECR-091273 | 07FEB20 | R.AMPARO | CUSTOMER EVAL BOARD Z
DIMENSION: (REF) | DIA MAX | +2/-0 MILS | - | " "
User.11: A | C
User.12: A | C
